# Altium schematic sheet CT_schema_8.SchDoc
size 254 x 194 mm
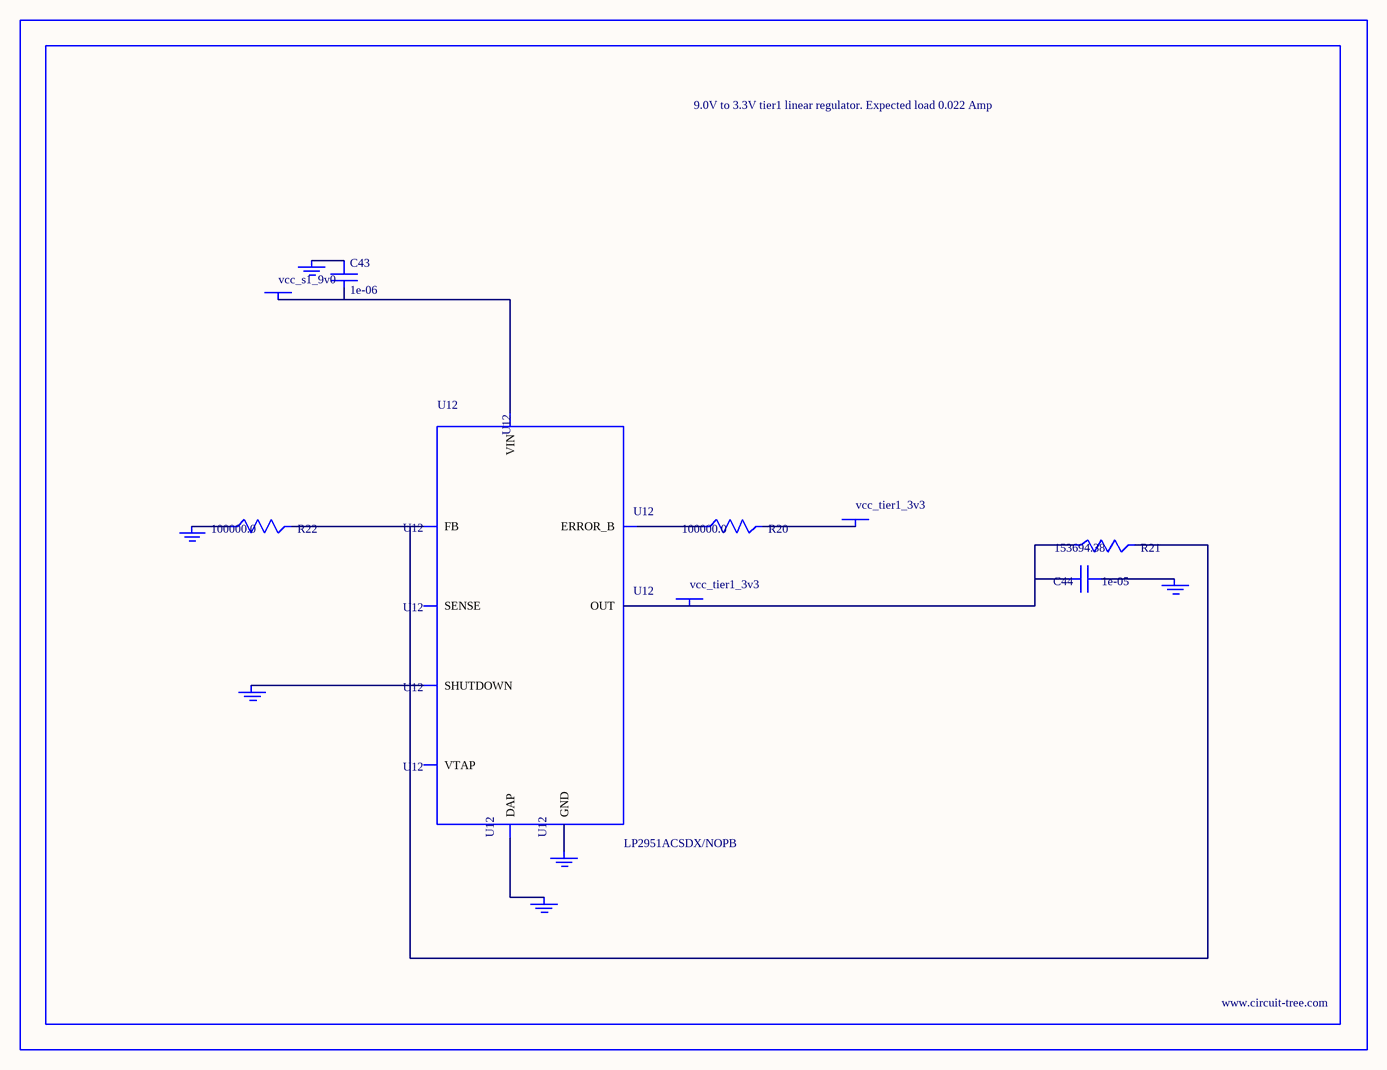
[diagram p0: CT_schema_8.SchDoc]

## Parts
BORDER7  (no value)
C43  1e-06  [C0603]
C44  1e-05  [C1210]
GND_INSTANCE_7_0  (no value)
GND_INSTANCE_7_1  (no value)
GND_INSTANCE_7_2  (no value)
GND_INSTANCE_7_3  (no value)
GND_INSTANCE_7_4  (no value)
GND_INSTANCE_7_5  (no value)
POWER_INSTANCE_7_0  vcc_tier1_3v3
POWER_INSTANCE_7_1  vcc_s1_9v0
POWER_INSTANCE_7_2  vcc_tier1_3v3
R20  100000.0  [R0603]
R21  153694.38  [R0603]
R22  100000.0  [R0603]
U12  LP2951ACSDX/NOPB  [WSON-8]

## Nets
NetC43_1: C43.1 GND_INSTANCE_7_3.0(GND)
NetC43_2: C43.2 POWER_INSTANCE_7_1.0(PWR) U12.8(VIN)
NetC44_1: C44.1 GND_INSTANCE_7_0.0(GND)
NetC44_2: C44.2 POWER_INSTANCE_7_2.0(PWR) R21.1 U12.1(OUT)
NetGND_INSTANCE_7_1_0: GND_INSTANCE_7_1.0(GND) U12.3(SHUTDOWN)
NetGND_INSTANCE_7_2_0: GND_INSTANCE_7_2.0(GND) R22.1
NetGND_INSTANCE_7_4_0: GND_INSTANCE_7_4.0(GND) U12.PAD(DAP)
NetGND_INSTANCE_7_5_0: GND_INSTANCE_7_5.0(GND) U12.4(GND)
NetPOWER_INSTANCE_7_0_0: POWER_INSTANCE_7_0.0(PWR) R20.2
NetR20_1: R20.1 U12.5(ERROR_B)
NetR21_2: R21.2 R22.2 U12.7(FB)

Not connected (* = marked no-connect by the designer): U12 2(SENSE) 6(VTAP)

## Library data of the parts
BORDER7 = BORDER_PAGE7
C43 = C0603C105K3RACTU
C44 = GRM32DR61E106MA12L
GND_INSTANCE_7_0-GND_INSTANCE_7_5 = GND
POWER_INSTANCE_7_0-POWER_INSTANCE_7_2 = PWR
R20 R22 = RC0603JR-07100KL
R21 = R21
